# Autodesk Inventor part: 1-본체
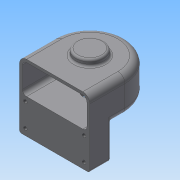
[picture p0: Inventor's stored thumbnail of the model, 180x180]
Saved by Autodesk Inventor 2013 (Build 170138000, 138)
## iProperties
Created: 2015-02
Part Number: 1-본체
Material: 일반
Document SubType Name: Modeling
Designer: Administrator
Density: 1 g/cm^3
Author: Administrator
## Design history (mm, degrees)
sketch "스케치1"
  geometry: L1 (-50, 0)-(-50, -50); L2 (-50, -50)-(50, -50); L3 (50, -50)-(50, 0); A1 r 50 centre (0, 0) between (-50, 0) and (50, 0); 1 further point
  constraints: 6 end point, 2 point on circle, 2 tangent, 1 centre point, 1 coincident, 1 horizontal, 1 parallel, 1 vertical
  dimensions: "d0" = 100 diameter of A1; "d2" = 50 distance from line of L2 point (0, 0)
extrude "돌출1" new body sketch "스케치1" distance "d3" = 50; taper "d4" = 0 deg
sketch "스케치2"
  geometry: L1 (-50, 0)-(-50, -50) reference; L2 (-50, -50)-(50, -50) reference; L3 (50, -50)-(50, 0) reference; L4 (-50, -50)-(50, -50); L5 (50, -50)-(50, -20); L6 (50, -20)-(-50, -20); L7 (-50, -20)-(-50, -50); L8 (-50, -50)-(50, -20); L9 (50, -50)-(-50, -20); 1 further point
  constraints: 12 end point, 3 collinear, 2 midpoint, 2 parallel, 1 horizontal, 1 perpendicular
  dimensions: "d5" = 30 distance between parallel lines of L2 L6
extrude "돌출2" join sketch "스케치2" distance "d6" = 95; taper "d7" = 0 deg
sketch "스케치3"
  geometry: L1 (-50, -20)-(50, -20) reference; A1 r 50 centre (0, 0) between (50, 0) and (-50, 0) reference; A2 r 40 centre (0, 0) between (-34.641, -20) and (34.641, -20)
  constraints: 2 point on circle, 2 point on line, 1 centre point, 1 coincident
  dimensions: "d8" = 80 diameter of A2
extrude "돌출3" cut sketch "스케치3" stored distance "d10" = 95; taper "d11" = 0 deg
sketch "스케치4"
  geometry: C1 r 25 at (0, 0); A1 r 50 centre (0, 0) between (50, 0) and (-50, 0) reference
  constraints: 1 centre point, 1 coincident
  dimensions: "d12" = 50 diameter of C1
extrude "돌출4" join sketch "스케치4" distance "d14" = 10; taper "d15" = -20 deg
sketch "스케치5"
  geometry: C1 r 20 at (0, 0); A1 r 50 centre (0, 0) between (50, 0) and (-50, 0) reference
  constraints: 1 centre point, 1 coincident
  dimensions: "d16" = 40 diameter of C1
extrude "돌출5" join sketch "스케치5" distance "d18" = 9; taper "d19" = 0 deg
node "작업 평면1"
sketch "스케치7"
  geometry: L1 (-50, 0)-(-50, -50) reference; L2 (-50, -50)-(50, -50) reference; L3 (50, -50)-(50, 0) reference; L4 (46, 0)-(46, -50); L5 (-46, -50)-(-46, 0); L6 (-46, -50)-(46, -50); A1 r 50 centre (0, 0) between (50, 0) and (-50, 0) reference; A2 r 46 centre (0, 0) between (46, 0) and (-46, 0); 1 further point
  constraints: 6 end point, 2 point on circle, 2 point on line, 1 centre point, 1 collinear
  dimensions: "d21" = 4 radial gap between concentric circles of A1 A2; "d24" = 4 distance between parallel lines of L5 L1; "d25" = 4 distance between parallel lines of L3 L4
extrude "돌출6" cut sketch "스케치7" distance "d22" = 42; taper "d23" = 0 deg
hole "구멍1" diameter "d28" = 20; stored, may be unused: countersink angle "d32" = 90 deg, drill point angle "d34" = 0 deg; dims "d26" = 10, "d27" = 10, "d29" = 6, "d30" = 28, "d31" = 10, "d33" = 14
sketch "스케치8"
  geometry: A1 r 46 centre (0, 0) between (46, 0) and (-46, 0) reference; 1 further point
  constraints: 1 coincident
hole "구멍2" sketch "스케치8" at (0, 0) diameter "d35" = 20; stored, may be unused: countersink angle "d39" = 90 deg, drill point angle "d41" = 0 deg; dims "d36" = 6, "d37" = 28, "d38" = 8, "d40" = 10
sketch "스케치9"
  geometry: L1 (100, -95)-(0, -95) reference; L2 (91.75, -86)-(8.25, -86); L3 (8.25, -86)-(8.25, -53); L4 (8.25, -53)-(91.75, -53); L5 (91.75, -53)-(91.75, -86); L6 (91.75, -86)-(8.25, -53); L7 (8.25, -86)-(91.75, -53); 7 further points
  constraints: 12 end point, 4 coincident, 3 midpoint, 2 parallel, 1 horizontal, 1 perpendicular, 1 vertical alignment
  dimensions: "d42" = 33 distance of L2.end L3.end; "d44" = 83.5 distance of L2.start L2.end; "d45" = 9 distance between parallel lines of L2 L1
hole "구멍3" sketch "스케치9" at (8.25, -86), (8.25, -53), (91.75, -86), (91.75, -53) diameter "d46" = 5.134; stored, may be unused: countersink angle "d50" = 90 deg, drill point angle "d52" = 0 deg; dims "d47" = 10, "d48" = 28, "d49" = 8, "d51" = 13
sketch "스케치10"
  geometry: C1 r 14 at (0, 0) reference; C2 r 21.36 at (0, 0) reference; A1 r 18 centre (0, 0) between (0, 18) and (18, 0); 2 further points
  constraints: 4 point on circle, 2 horizontal alignment, 2 vertical alignment, 1 centre point, 1 coincident
  dimensions: "d53" = 36 diameter of A1
hole "구멍4" sketch "스케치10" at (0, 18), (18, 0), (-18, 0), (0, -18) diameter "d55" = 2.459; stored, may be unused: countersink angle "d59" = 90 deg, drill point angle "d61" = 0 deg; dims "d56" = 6, "d57" = 28, "d58" = 8, "d60" = 9
fillet "모깎기1" dims "d62" = 10
fillet "모깎기2" dims "d63" = 3
node "작업 평면2"
sketch "스케치11"
  geometry: L1 (-40, 50)-(40, 50) reference; 3 further points
  constraints: 1 midpoint, 1 vertical alignment, 1 other
  dimensions: "d64" = 25 distance from line of point (0, 25) L1
feature "엠보싱1" sketch "스케치11" dims "d0" = 100, "d2" = 50, "d65" = 0.5, "d66" = 0
fillet "모깎기3" dims "d67" = 6
fillet "모깎기4" dims "d68" = 0.3
chamfer "모따기1" distance "d69" = 1; stored, may be unused: second distance "d70" = 2, angle "d71" = 45 deg
fillet "모깎기5" dims "d72" = 3
node "솔리드1"
other parameters: "d20" = -4
